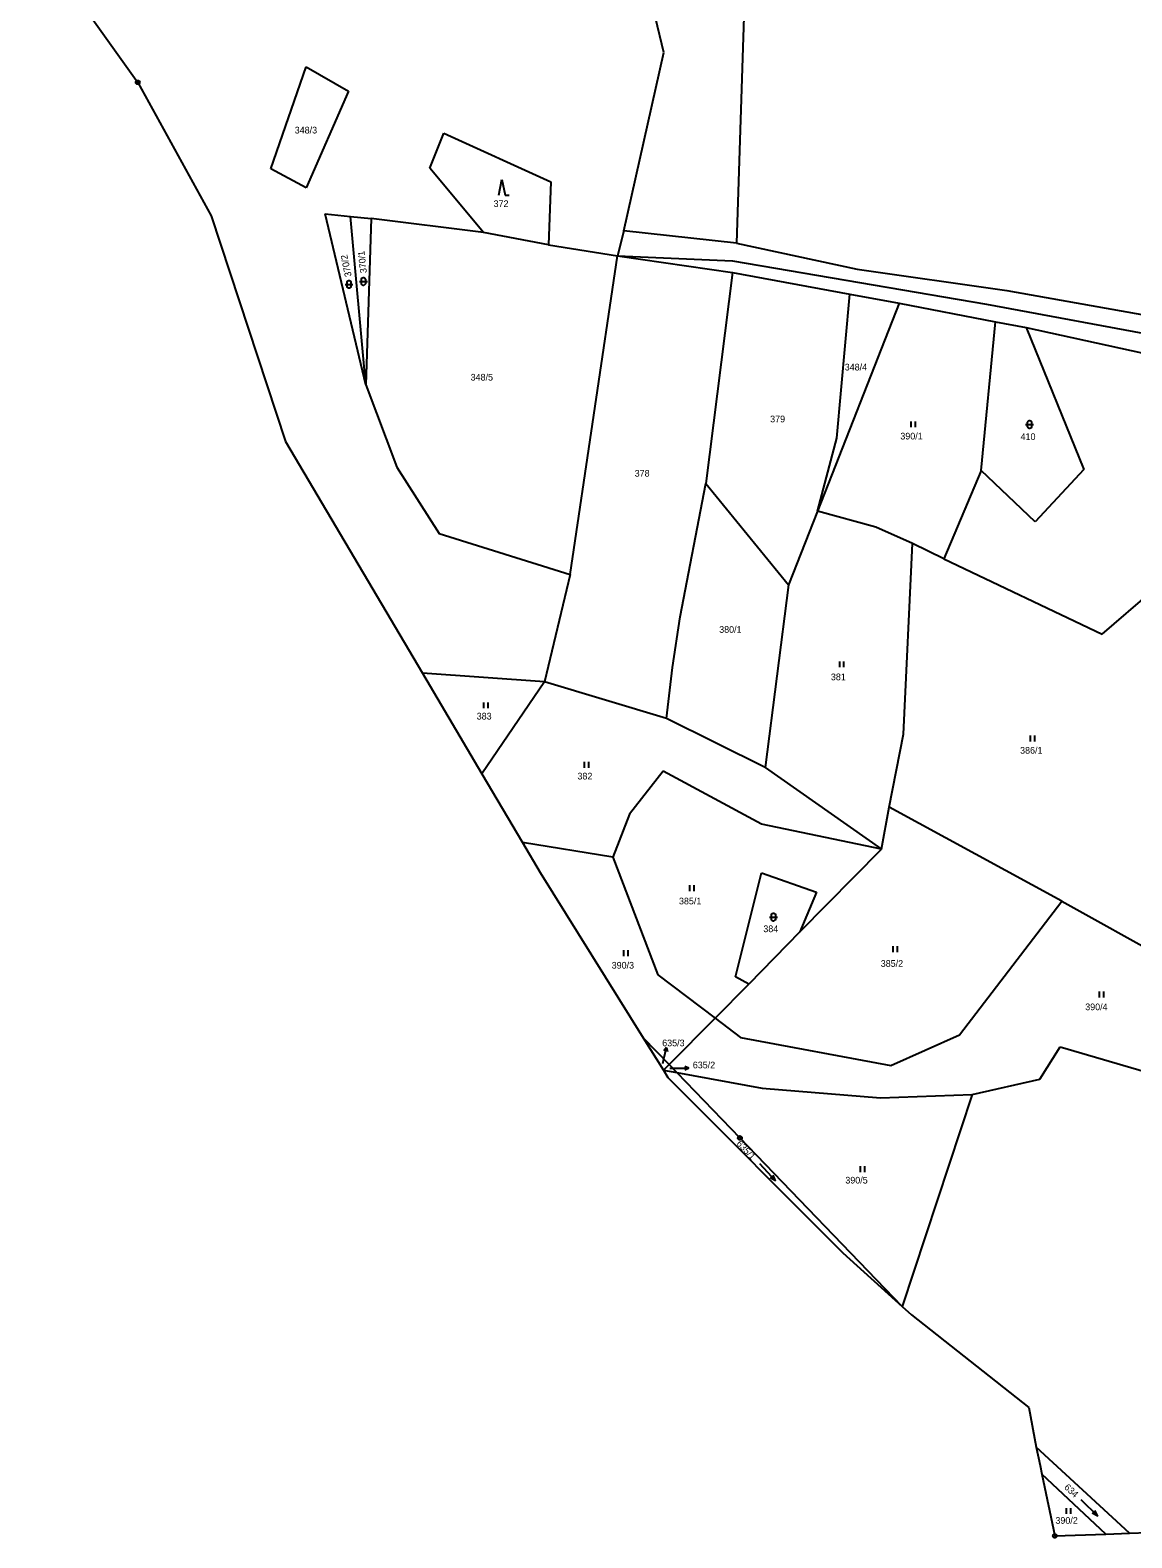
# Model space of a CAD drawing. Extents: x -794421 to -792735, y -1117671 to -1115559.
# Drawn here: x -794313 to -794032.7, y -1117487.3 to -1117103.6 of the extents above; entities that cross this region are included whole.
import ezdxf

# ---------------------------------------------------------------- set-up
doc = ezdxf.new("R2010")
doc.units = 0
for name, color, linetype in [('Komunikace', 7, 'Continuous'), ('Vrstva 1', 7, 'Continuous'), ('Vrstva 14', 7, 'Continuous'), ('Vrstva 16', 7, 'Continuous'), ('Vrstva 23', 7, 'Continuous'), ('Vrstva 28', 7, 'Continuous'), ('Vrstva 4', 7, 'Continuous')]:
    doc.layers.add(name, color=color, linetype=linetype)

msp = doc.modelspace()

# ---------------------------------------------------------------- linework, layer by layer
at = {"layer": 'Komunikace'}
for p, q in [((-794151.97, -1117366.55), (-794151.71, -1117365.39)), ((-794150.19, -1117367.8), (-794148.38, -1117367.8))]:
    msp.add_line(p, q, dxfattribs=at)
at = {"layer": 'Vrstva 1'}
for p, q in [((-794131, -1117087.43), (-794133.24, -1117157.84)), ((-794151.74, -1117109.25), (-794153.88, -1117100.48)), ((-794161.96, -1117154.68), (-794151.74, -1117109.25)), ((-794251.74, -1117138.87), (-794242.76, -1117112.97)), ((-794242.76, -1117112.97), (-794231.95, -1117119.14)), ((-794231.95, -1117119.14), (-794242.76, -1117143.73)), ((-794211.29, -1117138.7), (-794207.72, -1117129.77)), ((-794207.72, -1117129.77), (-794180.46, -1117142.2)), ((-794242.76, -1117143.73), (-794251.74, -1117138.87)), ((-794197.61, -1117155.07), (-794211.29, -1117138.7)), ((-794180.46, -1117142.2), (-794181.06, -1117158.23)), ((-794227.57, -1117193.88), (-794237.89, -1117150.38)), ((-794237.89, -1117150.38), (-794231.45, -1117151.01)), ((-794231.45, -1117151.01), (-794226.21, -1117151.52)), ((-794227.57, -1117193.88), (-794231.45, -1117151.01)), ((-794226.21, -1117151.52), (-794227.57, -1117193.88)), ((-794197.61, -1117155.07), (-794226.21, -1117151.52)), ((-794161.96, -1117154.68), (-794163.51, -1117161.01)), ((-794133.24, -1117157.84), (-794161.96, -1117154.68)), ((-794181.06, -1117158.23), (-794197.61, -1117155.07)), ((-794181.06, -1117158.23), (-794163.51, -1117161.01)), ((-794133.24, -1117157.84), (-794102.58, -1117164.39)), ((-794175.54, -1117242.09), (-794163.51, -1117161.01)), ((-794163.51, -1117161.01), (-794134.29, -1117162.33)), ((-794163.51, -1117161.01), (-794134.28, -1117165.27)), ((-794134.29, -1117162.33), (-794069.63, -1117173.34)), ((-794134.28, -1117165.27), (-794141.07, -1117219.01)), ((-794134.28, -1117165.27), (-794104.43, -1117170.79)), ((-794102.58, -1117164.39), (-794064.52, -1117169.88)), ((-794064.52, -1117169.88), (-794016.07, -1117178.47)), ((-794091.9, -1117173.1), (-794112.65, -1117226)), ((-794107.72, -1117207.43), (-794104.43, -1117170.79)), ((-794104.43, -1117170.79), (-794091.9, -1117173.1)), ((-794091.9, -1117173.1), (-794067.34, -1117177.84)), ((-794069.63, -1117173.34), (-794018.51, -1117182.79)), ((-794071.01, -1117215.66), (-794067.34, -1117177.84)), ((-794067.34, -1117177.84), (-794059.57, -1117179.25)), ((-794059.57, -1117179.25), (-794044.88, -1117215.44)), ((-794059.57, -1117179.25), (-794022.04, -1117187.47)), ((-794227.57, -1117193.88), (-794219.65, -1117214.84)), ((-794112.65, -1117226), (-794107.72, -1117207.43)), ((-794219.65, -1117214.84), (-794208.91, -1117231.69)), ((-794071.01, -1117215.66), (-794080.49, -1117238.13)), ((-794057.3, -1117228.73), (-794071.01, -1117215.66)), ((-794044.88, -1117215.44), (-794057.3, -1117228.73)), ((-794147.63, -1117252.89), (-794141.07, -1117219.01)), ((-794141.07, -1117219.01), (-794120.01, -1117244.75)), ((-794112.65, -1117226), (-794120.01, -1117244.75)), ((-794097.81, -1117230.11), (-794112.65, -1117226)), ((-794088.5, -1117234.2), (-794097.81, -1117230.11)), ((-794208.91, -1117231.69), (-794175.54, -1117242.09)), ((-794090.79, -1117282.73), (-794088.5, -1117234.2)), ((-794080.49, -1117238.13), (-794088.5, -1117234.2)), ((-794080.49, -1117238.13), (-794040.25, -1117257.3)), ((-794175.54, -1117242.09), (-794182.07, -1117269.4)), ((-794120.01, -1117244.75), (-794125.98, -1117291.26)), ((-794040.25, -1117257.3), (-794027.44, -1117246.25)), ((-794149.57, -1117265.78), (-794147.63, -1117252.89)), ((-794151.09, -1117278.81), (-794149.57, -1117265.78)), ((-794182.07, -1117269.4), (-794213.19, -1117267.22)), ((-794182.07, -1117269.4), (-794198.03, -1117292.84)), ((-794151.09, -1117278.81), (-794182.07, -1117269.4)), ((-794125.98, -1117291.26), (-794151.09, -1117278.81)), ((-794094.39, -1117301.31), (-794090.79, -1117282.73)), ((-794151.92, -1117292.14), (-794160.45, -1117303.16)), ((-794126.93, -1117305.65), (-794151.92, -1117292.14)), ((-794125.98, -1117291.26), (-794096.41, -1117312.05)), ((-794160.45, -1117303.16), (-794164.71, -1117314.06)), ((-794096.41, -1117312.05), (-794094.39, -1117301.31)), ((-794050.52, -1117325.23), (-794094.39, -1117301.31)), ((-794096.41, -1117312.05), (-794126.93, -1117305.65)), ((-794164.71, -1117314.06), (-794187.67, -1117310.36)), ((-794117.13, -1117333.07), (-794096.41, -1117312.05)), ((-794164.71, -1117314.06), (-794153.26, -1117344.02)), ((-794133.48, -1117344.5), (-794126.88, -1117318.09)), ((-794126.88, -1117318.09), (-794112.9, -1117322.94)), ((-794112.9, -1117322.94), (-794117.13, -1117333.07)), ((-794076.52, -1117359.27), (-794050.52, -1117325.23)), ((-794050.52, -1117325.23), (-794020.24, -1117342.12)), ((-794117.13, -1117333.07), (-794130.12, -1117346.41)), ((-794153.26, -1117344.02), (-794138.71, -1117355.05)), ((-794138.71, -1117355.05), (-794130.12, -1117346.41)), ((-794130.12, -1117346.41), (-794133.48, -1117344.5)), ((-794150.43, -1117366.83), (-794138.71, -1117355.05)), ((-794138.71, -1117355.05), (-794132.28, -1117359.92)), ((-794157.02, -1117360), (-794150.43, -1117366.83)), ((-794132.28, -1117359.92), (-794094.01, -1117367.08)), ((-794094.01, -1117367.08), (-794076.52, -1117359.27)), ((-794056.12, -1117370.58), (-794050.89, -1117362.31)), ((-794050.89, -1117362.31), (-794015.76, -1117372.63)), ((-794151.87, -1117368.28), (-794150.43, -1117366.83)), ((-794151.87, -1117368.28), (-794148.43, -1117368.9)), ((-794150.43, -1117366.83), (-794148.43, -1117368.9)), ((-794148.43, -1117368.9), (-794126.73, -1117372.84)), ((-794148.43, -1117368.9), (-794132.4, -1117385.51)), ((-794126.73, -1117372.84), (-794096.59, -1117375.35)), ((-794073.33, -1117374.49), (-794056.12, -1117370.58)), ((-794096.59, -1117375.35), (-794073.33, -1117374.49)), ((-794073.33, -1117374.49), (-794091.13, -1117428.39)), ((-794091.13, -1117428.39), (-794132.4, -1117385.51)), ((-794033.25, -1117486.1), (-794057.01, -1117464.25)), ((-794039.32, -1117486.32), (-794055.56, -1117471.12))]:
    msp.add_line(p, q, dxfattribs=at)
at = {"layer": 'Vrstva 16'}
for p, q in [((-794151.051, -1117362.463), (-794151.758, -1117363.329)), ((-794151.71, -1117365.39), (-794151.051, -1117362.463)), ((-794151.051, -1117362.463), (-794150.783, -1117363.548)), ((-794148.38, -1117367.8), (-794145.38, -1117367.8)), ((-794145.38, -1117367.8), (-794146.38, -1117367.3)), ((-794145.38, -1117367.8), (-794146.38, -1117368.3))]:
    msp.add_line(p, q, dxfattribs=at)
at = {"layer": 'Vrstva 23'}
for p, q in [((-794193.74, -1117145.57), (-794192.94, -1117141.57)), ((-794192.94, -1117141.57), (-794192.14, -1117145.57)), ((-794192.14, -1117145.57), (-794191.14, -1117145.57)), ((-794232.84, -1117168.29), (-794230.84, -1117168.29)), ((-794232.34, -1117167.69), (-794232.24, -1117167.49)), ((-794232.34, -1117168.89), (-794232.34, -1117167.69)), ((-794232.24, -1117169.09), (-794232.34, -1117168.89)), ((-794232.24, -1117167.49), (-794232.14, -1117167.39)), ((-794232.14, -1117169.19), (-794232.24, -1117169.09)), ((-794232.14, -1117167.39), (-794231.94, -1117167.29)), ((-794231.94, -1117169.29), (-794232.14, -1117169.19)), ((-794231.94, -1117167.29), (-794231.74, -1117167.29)), ((-794231.74, -1117169.29), (-794231.94, -1117169.29)), ((-794231.74, -1117167.29), (-794231.54, -1117167.39)), ((-794231.54, -1117169.19), (-794231.74, -1117169.29)), ((-794231.54, -1117167.39), (-794231.44, -1117167.49)), ((-794231.44, -1117169.09), (-794231.54, -1117169.19)), ((-794231.44, -1117167.49), (-794231.34, -1117167.69)), ((-794231.34, -1117168.89), (-794231.44, -1117169.09)), ((-794231.34, -1117167.69), (-794231.34, -1117168.89)), ((-794229.18, -1117167.54), (-794227.18, -1117167.54)), ((-794228.68, -1117166.94), (-794228.58, -1117166.74)), ((-794228.68, -1117168.14), (-794228.68, -1117166.94)), ((-794228.58, -1117168.34), (-794228.68, -1117168.14)), ((-794228.58, -1117166.74), (-794228.48, -1117166.64)), ((-794228.48, -1117168.44), (-794228.58, -1117168.34)), ((-794228.48, -1117166.64), (-794228.28, -1117166.54)), ((-794228.28, -1117168.54), (-794228.48, -1117168.44)), ((-794228.28, -1117166.54), (-794228.08, -1117166.54)), ((-794228.08, -1117168.54), (-794228.28, -1117168.54)), ((-794228.08, -1117166.54), (-794227.88, -1117166.64)), ((-794227.88, -1117168.44), (-794228.08, -1117168.54)), ((-794227.88, -1117166.64), (-794227.78, -1117166.74)), ((-794227.78, -1117168.34), (-794227.88, -1117168.44)), ((-794227.78, -1117166.74), (-794227.68, -1117166.94)), ((-794227.68, -1117168.14), (-794227.78, -1117168.34)), ((-794227.68, -1117166.94), (-794227.68, -1117168.14)), ((-794088.81, -1117204.65), (-794088.81, -1117203.15)), ((-794087.81, -1117203.15), (-794087.81, -1117204.65)), ((-794059.7, -1117203.96), (-794057.7, -1117203.96)), ((-794059.2, -1117203.36), (-794059.1, -1117203.16)), ((-794059.2, -1117204.56), (-794059.2, -1117203.36)), ((-794059.1, -1117204.76), (-794059.2, -1117204.56)), ((-794059.1, -1117203.16), (-794059, -1117203.06)), ((-794059, -1117203.06), (-794058.8, -1117202.96)), ((-794058.8, -1117202.96), (-794058.6, -1117202.96)), ((-794058.6, -1117202.96), (-794058.4, -1117203.06)), ((-794058.4, -1117203.06), (-794058.3, -1117203.16)), ((-794058.3, -1117203.16), (-794058.2, -1117203.36)), ((-794058.2, -1117204.56), (-794058.3, -1117204.76)), ((-794058.2, -1117203.36), (-794058.2, -1117204.56)), ((-794059, -1117204.86), (-794059.1, -1117204.76)), ((-794058.8, -1117204.96), (-794059, -1117204.86)), ((-794058.6, -1117204.96), (-794058.8, -1117204.96)), ((-794058.4, -1117204.86), (-794058.6, -1117204.96)), ((-794058.3, -1117204.76), (-794058.4, -1117204.86)), ((-794107.01, -1117265.73), (-794107.01, -1117264.23)), ((-794106.01, -1117264.23), (-794106.01, -1117265.73)), ((-794197.51, -1117276.16), (-794197.51, -1117274.66)), ((-794196.51, -1117274.66), (-794196.51, -1117276.16)), ((-794058.49, -1117284.64), (-794058.49, -1117283.14)), ((-794057.49, -1117283.14), (-794057.49, -1117284.64)), ((-794171.9, -1117291.33), (-794171.9, -1117289.83)), ((-794170.9, -1117289.83), (-794170.9, -1117291.33)), ((-794145.12, -1117322.72), (-794145.12, -1117321.22)), ((-794144.12, -1117321.22), (-794144.12, -1117322.72)), ((-794124.86, -1117329.31), (-794122.86, -1117329.31)), ((-794124.36, -1117328.71), (-794124.26, -1117328.51)), ((-794124.36, -1117329.91), (-794124.36, -1117328.71)), ((-794124.26, -1117330.11), (-794124.36, -1117329.91)), ((-794124.26, -1117328.51), (-794124.16, -1117328.41)), ((-794124.16, -1117330.21), (-794124.26, -1117330.11)), ((-794124.16, -1117328.41), (-794123.96, -1117328.31)), ((-794123.96, -1117330.31), (-794124.16, -1117330.21)), ((-794123.96, -1117328.31), (-794123.76, -1117328.31)), ((-794123.76, -1117330.31), (-794123.96, -1117330.31)), ((-794123.76, -1117328.31), (-794123.56, -1117328.41)), ((-794123.56, -1117330.21), (-794123.76, -1117330.31)), ((-794123.56, -1117328.41), (-794123.46, -1117328.51)), ((-794123.46, -1117330.11), (-794123.56, -1117330.21)), ((-794123.46, -1117328.51), (-794123.36, -1117328.71)), ((-794123.36, -1117329.91), (-794123.46, -1117330.11)), ((-794123.36, -1117328.71), (-794123.36, -1117329.91)), ((-794161.91, -1117339.25), (-794161.91, -1117337.75)), ((-794160.91, -1117337.75), (-794160.91, -1117339.25)), ((-794093.37, -1117338.23), (-794093.37, -1117336.73)), ((-794092.37, -1117336.73), (-794092.37, -1117338.23)), ((-794040.91, -1117349.79), (-794040.91, -1117348.29)), ((-794039.91, -1117348.29), (-794039.91, -1117349.79)), ((-794127.426, -1117392.045), (-794123.313, -1117396.414)), ((-794101.71, -1117394.22), (-794101.71, -1117392.72)), ((-794100.71, -1117392.72), (-794100.71, -1117394.22)), ((-794123.313, -1117396.414), (-794124.706, -1117395.664)), ((-794123.313, -1117396.414), (-794123.977, -1117394.979)), ((-794049.32, -1117481.2), (-794049.32, -1117479.7)), ((-794048.32, -1117479.7), (-794048.32, -1117481.2)), ((-794045.648, -1117477.566), (-794041.331, -1117481.733)), ((-794041.331, -1117481.733), (-794042.063, -1117480.331)), ((-794041.331, -1117481.733), (-794042.757, -1117481.051))]:
    msp.add_line(p, q, dxfattribs=at)
at = {"layer": 'Vrstva 28'}
for centre, radius in [((-794285.59, -1117116.88), 0.5), ((-794285.59, -1117116.88), 0.01), ((-794132.4, -1117385.51), 0.5), ((-794132.4, -1117385.51), 0.01), ((-794052.27, -1117486.79), 0.5), ((-794052.27, -1117486.79), 0.01)]:
    msp.add_circle(centre, radius, dxfattribs=at)
at = {"layer": 'Vrstva 4'}
for p, q in [((-794312.96, -1117078.48), (-794285.59, -1117116.88)), ((-794285.59, -1117116.88), (-794266.87, -1117150.88)), ((-794266.87, -1117150.88), (-794248.04, -1117208.29)), ((-794248.04, -1117208.29), (-794213.19, -1117267.22)), ((-794213.19, -1117267.22), (-794198.03, -1117292.84)), ((-794198.03, -1117292.84), (-794187.67, -1117310.36)), ((-794187.67, -1117310.36), (-794183.18, -1117317.96)), ((-794183.18, -1117317.96), (-794157.02, -1117360)), ((-794157.02, -1117360), (-794151.87, -1117368.28)), ((-794151.87, -1117368.28), (-794150.73, -1117370.12)), ((-794150.73, -1117370.12), (-794106.24, -1117414.73)), ((-794106.24, -1117414.73), (-794091.13, -1117428.39)), ((-794091.13, -1117428.39), (-794088.72, -1117430.57)), ((-794088.72, -1117430.57), (-794058.89, -1117454.08)), ((-794058.89, -1117454.08), (-794057.01, -1117464.25)), ((-794057.01, -1117464.25), (-794056.03, -1117468.91)), ((-794056.03, -1117468.91), (-794055.56, -1117471.12)), ((-794055.56, -1117471.12), (-794052.27, -1117486.79)), ((-794033.25, -1117486.1), (-793982.31, -1117484.24)), ((-794052.27, -1117486.79), (-794039.32, -1117486.32)), ((-794039.32, -1117486.32), (-794033.25, -1117486.1))]:
    msp.add_line(p, q, dxfattribs=at)

# ---------------------------------------------------------------- texts
at = {"layer": 'Vrstva 14'}
for s, height, p in [('348/3', 1.7, (-794245.656, -1117129.89)), ('372', 1.7, (-794195.063, -1117148.6)), ('348/4', 1.7, (-794105.731, -1117190.2)), ('348/5', 1.7, (-794200.902, -1117192.77)), ('379', 1.7, (-794124.703, -1117203.39)), ('390/1', 1.7, (-794091.582, -1117207.76)), ('410', 1.7, (-794060.985, -1117207.88)), ('378', 1.7, (-794159.173, -1117217.22)), ('380/1', 1.7, (-794137.672, -1117256.97)), ('381', 1.7, (-794109.25, -1117269.04)), ('383', 1.7, (-794199.357, -1117279.03)), ('386/1', 1.7, (-794061.113, -1117287.73)), ('382', 1.7, (-794173.726, -1117294.29)), ('385/1', 1.7, (-794147.899, -1117326.08)), ('384', 1.7, (-794126.442, -1117333.15)), ('390/3', 1.7, (-794165.019, -1117342.42)), ('385/2', 1.7, (-794096.566, -1117341.97)), ('390/4', 1.7, (-794044.545, -1117353.01)), ('635/3', 0.1, (-794152.178, -1117366.55)), ('635/2', 0.1, (-794150.397, -1117367.8)), ('390/5', 1.7, (-794105.576, -1117397.12)), ('390/2', 1.7, (-794052.129, -1117483.71))]:
    msp.add_text(s, height=height, dxfattribs=at).set_placement(p)
for s, rotation, p in [('370/2', 101.63097, (-794231.177, -1117166.183)), ('370/1', 96.4386, (-794227.298, -1117165.348)), ('635/1', 313.30701, (-794133.393, -1117387.088)), ('634', 317.29293, (-794050.046, -1117474.618))]:
    msp.add_text(s, height=1.7, rotation=rotation, dxfattribs=at).set_placement(p)
at = {"layer": 'Vrstva 16'}
for s, p in [('635/3', (-794152.17, -1117362.19)), ('635/2', (-794144.38, -1117367.8))]:
    msp.add_text(s, height=1.7, dxfattribs=at).set_placement(p)

doc.saveas('drawing.dxf')
